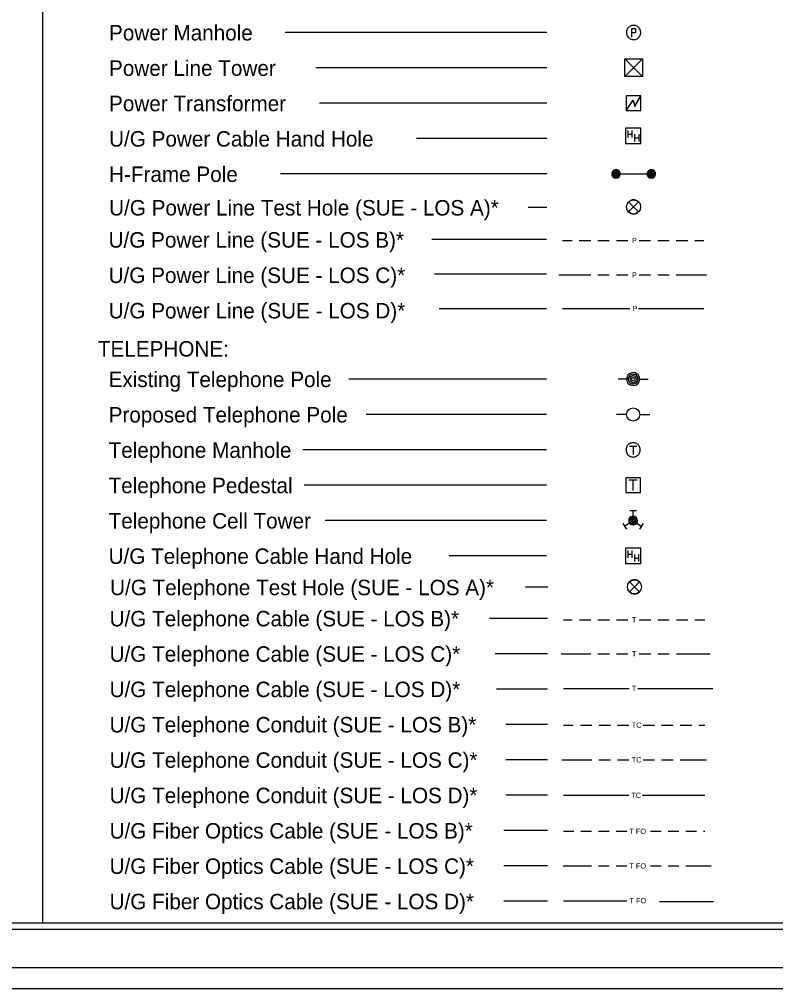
# Model space of a CAD drawing. Extents: x 811508 to 813252, y 647626 to 648754.
# Drawn here: x 812366 to 812809, y 647626 to 648193 of the extents above; entities that cross this region are included whole.
import ezdxf

# ---------------------------------------------------------------- set-up
doc = ezdxf.new("R2010")
doc.units = 0
for name, color, linetype in [('Exist Utilities Power Test Hole SUE LOS A CELL', 7, 'Continuous'), ('Exist Utilities Telephone Test Hole SUE LOS A CELL', 7, 'Continuous'), ('Sheet Cutting Line CELL', 7, 'Continuous'), ('Sheet Plot Border Inside CELL', 7, 'Continuous'), ('Sheet Plot Border Outside CELL', 7, 'Continuous'), ('Sheet_Plan', 7, 'Continuous'), ('Sheet_Symbology', 7, 'Continuous'), ('z - Construction', 7, 'Continuous')]:
    doc.layers.add(name, color=color, linetype=linetype)

msp = doc.modelspace()

# ---------------------------------------------------------------- linework, layer by layer
at = {"layer": 'Exist Utilities Power Test Hole SUE LOS A CELL'}
for points in [[(812728.98, 648086.07), (812723.13, 648080.22), (812726.06, 648083.15), (812723.13, 648086.07), (812728.98, 648080.22)], [(812723.13, 648086.07), (812726.06, 648083.15), (812728.98, 648086.07)], [(812728.98, 648080.22), (812726.06, 648083.15), (812723.13, 648080.22)]]:
    msp.add_lwpolyline(points, dxfattribs=at)
msp.add_circle((812726.06, 648083.15), 4.14, dxfattribs=at)
for start, end in [(45, 135), (225, 315)]:
    msp.add_arc((812726.06, 648083.15), 4.14, start, end, dxfattribs=at)
at = {"layer": 'Exist Utilities Telephone Test Hole SUE LOS A CELL'}
for points in [[(812729.47, 647863.71), (812723.62, 647857.86), (812726.55, 647860.78), (812723.62, 647863.71), (812729.47, 647857.86)], [(812723.62, 647863.71), (812726.55, 647860.78), (812729.47, 647863.71)], [(812729.47, 647857.86), (812726.55, 647860.78), (812723.62, 647857.86)]]:
    msp.add_lwpolyline(points, dxfattribs=at)
msp.add_circle((812726.55, 647860.78), 4.14, dxfattribs=at)
for start, end in [(45, 135), (225, 315)]:
    msp.add_arc((812726.55, 647860.78), 4.14, start, end, dxfattribs=at)
at = {"layer": 'Sheet Cutting Line CELL'}
msp.add_line((811533.6, 647637.99), (813217.6, 647637.99), dxfattribs=at)
at = {"layer": 'Sheet Plot Border Inside CELL'}
msp.add_lwpolyline([(811546.6, 647660.44), (813213.1, 647660.44), (813213.1, 648715.54), (811546.6, 648715.54)], close=True, dxfattribs=at)
at = {"layer": 'Sheet Plot Border Outside CELL'}
msp.add_lwpolyline([(811533.6, 647637.99), (813217.6, 647637.99), (813217.6, 648737.99), (811533.6, 648737.99)], close=True, dxfattribs=at)
at = {"layer": 'Sheet_Plan'}
msp.add_line((811546.61, 647664.09), (813213.5, 647664.09), dxfattribs=at)
at = {"layer": 'Sheet_Symbology'}
for p, q in [((812727.26, 648187.18), (812727.26, 648185.4)), ((812675.36, 648185.26), (812522.02, 648185.26)), ((812726.92, 648185.06), (812725.04, 648185.06)), ((812731.28, 648169.76), (812720.94, 648159.42)), ((812731.28, 648159.42), (812720.94, 648169.76)), ((812675.36, 648164.56), (812540.12, 648164.56)), ((812675.36, 648143.86), (812542.22, 648143.86)), ((812722.69, 648127.92), (812722.69, 648123.75)), ((812722.69, 648125.79), (812725.08, 648125.79)), ((812725.08, 648127.92), (812725.08, 648123.75)), ((812726.68, 648125.65), (812726.68, 648121.48)), ((812726.68, 648123.52), (812729.06, 648123.52)), ((812729.06, 648125.65), (812729.06, 648121.48)), ((812675.36, 648123.17), (812598.88, 648123.17)), ((812675.36, 648102.47), (812519.4, 648102.47)), ((812715.73, 648102.47), (812736.43, 648102.47)), ((812675.36, 648082.83), (812664.35, 648082.83)), ((812675.07, 648064.02), (812607.88, 648064.02)), ((812684.4, 648063.52), (812690.09, 648063.52)), ((812694.23, 648063.52), (812700.96, 648063.52)), ((812705.1, 648063.52), (812711.83, 648063.52)), ((812715.97, 648063.52), (812722.69, 648063.52)), ((812729.32, 648063.52), (812736.05, 648063.52)), ((812740.19, 648063.52), (812746.91, 648063.52)), ((812751.05, 648063.52), (812757.78, 648063.52)), ((812761.92, 648063.52), (812767.2, 648063.52)), ((812675.07, 648043.72), (812609.48, 648043.72)), ((812682.31, 648043.33), (812700.96, 648043.33)), ((812705.1, 648043.33), (812711.83, 648043.33)), ((812715.97, 648043.33), (812722.69, 648043.33)), ((812729.32, 648043.33), (812736.05, 648043.33)), ((812740.19, 648043.33), (812746.91, 648043.33)), ((812751.05, 648043.33), (812768.68, 648043.33)), ((812675.07, 648023.42), (812612.26, 648023.42)), ((812684.4, 648023.7), (812723.82, 648023.7)), ((812728.99, 648023.7), (812767.2, 648023.7)), ((812675.07, 647982.38), (812559.27, 647982.38)), ((812721.98, 647982.38), (812717.01, 647982.38)), ((812729.62, 647982.38), (812734.59, 647982.38)), ((812675.07, 647961.68), (812569.44, 647961.68)), ((812721.96, 647961.67), (812716.14, 647961.67)), ((812729.72, 647961.67), (812735.54, 647961.67)), ((812727.95, 647942.93), (812723.68, 647942.93)), ((812725.8, 647942.93), (812725.8, 647938.22)), ((812675.07, 647940.98), (812532.39, 647940.98)), ((812675.07, 647920.28), (812533.11, 647920.28)), ((812723.38, 647923.4), (812728.22, 647923.4)), ((812725.8, 647917.16), (812725.8, 647923.4)), ((812723.86, 647905.44), (812727.74, 647905.44)), ((812725.8, 647902.13), (812725.8, 647905.44)), ((812675.07, 647899.58), (812545.47, 647899.58)), ((812722.12, 647894.64), (812719.89, 647897.82)), ((812723.72, 647898.13), (812721.01, 647896.23)), ((812727.89, 647898.13), (812730.6, 647896.23)), ((812731.71, 647897.82), (812729.49, 647894.64)), ((812722.63, 647882.01), (812722.63, 647877.84)), ((812722.63, 647879.89), (812725.01, 647879.89)), ((812725.01, 647882.01), (812725.01, 647877.84)), ((812726.61, 647879.74), (812726.61, 647875.57)), ((812728.99, 647879.74), (812728.99, 647875.57)), ((812675.07, 647878.88), (812618.11, 647878.88)), ((812726.61, 647877.62), (812728.99, 647877.62)), ((812675.92, 647860.59), (812662.82, 647860.59)), ((812675.64, 647842.35), (812641.71, 647842.35)), ((812684.97, 647841.52), (812690.17, 647841.52)), ((812694.31, 647841.52), (812701.03, 647841.52)), ((812705.17, 647841.52), (812711.9, 647841.52)), ((812716.04, 647841.52), (812722.77, 647841.52)), ((812729.39, 647841.52), (812736.12, 647841.52)), ((812740.26, 647841.52), (812746.99, 647841.52)), ((812751.13, 647841.52), (812757.85, 647841.52)), ((812761.99, 647841.52), (812767.76, 647841.52)), ((812675.64, 647821.65), (812644.98, 647821.65)), ((812683.67, 647821.65), (812701.03, 647821.65)), ((812705.17, 647821.65), (812711.9, 647821.65)), ((812716.04, 647821.65), (812722.77, 647821.65)), ((812729.39, 647821.65), (812736.12, 647821.65)), ((812740.26, 647821.65), (812746.99, 647821.65)), ((812751.13, 647821.65), (812770.83, 647821.65)), ((812675.64, 647800.95), (812645.77, 647800.95)), ((812684.97, 647801.31), (812723.39, 647801.31)), ((812728.56, 647801.31), (812772.43, 647801.31)), ((812675.64, 647780.25), (812651.36, 647780.25)), ((812684.97, 647779.81), (812690.75, 647779.81)), ((812694.89, 647779.81), (812701.62, 647779.81)), ((812705.76, 647779.81), (812712.48, 647779.81)), ((812716.62, 647779.81), (812723.35, 647779.81)), ((812731.63, 647779.81), (812738.36, 647779.81)), ((812742.5, 647779.81), (812749.22, 647779.81)), ((812753.36, 647779.81), (812760.09, 647779.81)), ((812764.23, 647779.81), (812767.76, 647779.81)), ((812675.64, 647759.55), (812651.36, 647759.55)), ((812683.98, 647759.55), (812701.62, 647759.55)), ((812705.76, 647759.55), (812712.48, 647759.55)), ((812716.62, 647759.55), (812723.35, 647759.55)), ((812731.63, 647759.55), (812738.36, 647759.55)), ((812742.5, 647759.55), (812749.22, 647759.55)), ((812753.36, 647759.55), (812768.76, 647759.55)), ((812675.64, 647738.85), (812651.36, 647738.85)), ((812684.97, 647738.8), (812723.35, 647738.8)), ((812731.11, 647738.8), (812767.76, 647738.8)), ((812675.64, 647718.15), (812650.15, 647718.15)), ((812684.97, 647717.7), (812691.01, 647717.7)), ((812695.15, 647717.7), (812701.36, 647717.7)), ((812705.5, 647717.7), (812711.71, 647717.7)), ((812715.85, 647717.7), (812722.06, 647717.7)), ((812736.03, 647717.7), (812742.24, 647717.7)), ((812746.38, 647717.7), (812752.59, 647717.7)), ((812756.73, 647717.7), (812762.94, 647717.7)), ((812767.08, 647717.7), (812767.76, 647717.7)), ((812675.64, 647697.45), (812650.15, 647697.45)), ((812684.78, 647697.45), (812701.36, 647697.45)), ((812705.5, 647697.45), (812711.71, 647697.45)), ((812715.85, 647697.45), (812722.06, 647697.45)), ((812736.03, 647697.45), (812742.24, 647697.45)), ((812746.38, 647697.45), (812752.59, 647697.45)), ((812756.73, 647697.45), (812771.54, 647697.45)), ((812675.64, 647676.75), (812650.15, 647676.75)), ((812684.97, 647677.09), (812722.1, 647677.09)), ((812741.24, 647676.7), (812772.94, 647676.7))]:
    msp.add_line(p, q, dxfattribs=at)
for points in [[(812726.08, 648189.46), (812725.54, 648189.43), (812725.04, 648189.33), (812724.54, 648189.16), (812724.07, 648188.93), (812723.63, 648188.66), (812723.23, 648188.32), (812722.85, 648187.92), (812722.55, 648187.52), (812722.28, 648187.05), (812722.12, 648186.54), (812721.98, 648186.04), (812721.91, 648185.53), (812721.91, 648184.99), (812721.98, 648184.49), (812722.12, 648183.95), (812722.28, 648183.48), (812722.55, 648183.01), (812722.85, 648182.61), (812723.23, 648182.2), (812723.63, 648181.87), (812724.07, 648181.6), (812724.54, 648181.36), (812725.04, 648181.2), (812725.58, 648181.1), (812726.08, 648181.06), (812726.62, 648181.1), (812727.12, 648181.2), (812727.63, 648181.36), (812728.1, 648181.6), (812728.54, 648181.87), (812728.94, 648182.2), (812729.31, 648182.61), (812729.61, 648183.01), (812729.88, 648183.48), (812730.05, 648183.99), (812730.18, 648184.49), (812730.25, 648184.99), (812730.25, 648185.53), (812730.18, 648186.04), (812730.05, 648186.57), (812729.88, 648187.05), (812729.61, 648187.52), (812729.31, 648187.92), (812728.94, 648188.32), (812728.54, 648188.66), (812728.1, 648188.93), (812727.63, 648189.16), (812727.12, 648189.33), (812726.59, 648189.43), (812726.08, 648189.46)], [(812725.04, 648182.57), (812725.04, 648185.06), (812725.04, 648187.52), (812726.92, 648187.52)], [(812726.92, 648187.52), (812727.06, 648187.48), (812727.16, 648187.41), (812727.23, 648187.31), (812727.26, 648187.18)], [(812727.26, 648185.4), (812727.23, 648185.26), (812727.16, 648185.16), (812727.06, 648185.1), (812726.92, 648185.06)], [(812731.28, 648159.42), (812720.94, 648159.42), (812720.94, 648169.76), (812731.28, 648169.76), (812731.28, 648159.42), (812720.94, 648159.42), (812720.94, 648169.76), (812731.28, 648169.76), (812731.28, 648159.42)], [(812721.77, 648139.55), (812725.84, 648145.41), (812726.83, 648142.22), (812730.4, 648148.18)], [(812721.77, 648139.55), (812725.88, 648145.64), (812726.8, 648141.98), (812730.4, 648148.18)], [(812721.77, 648139.55), (812730.4, 648139.55), (812730.4, 648148.18), (812721.77, 648148.18), (812721.77, 648139.55)], [(812721.41, 648120.33), (812730.32, 648120.33), (812730.32, 648129.24), (812721.41, 648129.24), (812721.41, 648120.33)], [(812717.62, 648102.47), (812717.57, 648102.92), (812717.41, 648103.33), (812717.16, 648103.69), (812716.85, 648103.99), (812716.5, 648104.2), (812716.04, 648104.3), (812715.63, 648104.35), (812715.17, 648104.25), (812714.76, 648104.1), (812714.46, 648103.84), (812714.15, 648103.48), (812713.95, 648103.13), (812713.85, 648102.67), (812713.85, 648102.26), (812713.95, 648101.8), (812714.15, 648101.45), (812714.46, 648101.09), (812714.76, 648100.84), (812715.17, 648100.68), (812715.63, 648100.58), (812716.04, 648100.63), (812716.5, 648100.73), (812716.85, 648100.94), (812717.16, 648101.24), (812717.41, 648101.6), (812717.57, 648102.01), (812717.62, 648102.47)], [(812717.01, 648102.47), (812716.95, 648102.82), (812716.8, 648103.18), (812716.55, 648103.43), (812716.24, 648103.64), (812715.94, 648103.74), (812715.53, 648103.74), (812715.22, 648103.64), (812714.92, 648103.43), (812714.66, 648103.18), (812714.51, 648102.82), (812714.46, 648102.47), (812714.51, 648102.11), (812714.66, 648101.75), (812714.92, 648101.5), (812715.22, 648101.29), (812715.53, 648101.19), (812715.94, 648101.19), (812716.24, 648101.29), (812716.55, 648101.5), (812716.8, 648101.75), (812716.95, 648102.11), (812717.01, 648102.47)], [(812716.34, 648102.47), (812716.29, 648102.72), (812716.14, 648102.92), (812715.94, 648103.03), (812715.68, 648103.08), (812715.43, 648102.98), (812715.22, 648102.82), (812715.12, 648102.57), (812715.12, 648102.36), (812715.22, 648102.11), (812715.43, 648101.96), (812715.68, 648101.85), (812715.94, 648101.91), (812716.14, 648102.01), (812716.29, 648102.21), (812716.34, 648102.47)], [(812738.32, 648102.47), (812738.27, 648102.92), (812738.11, 648103.33), (812737.86, 648103.69), (812737.55, 648103.99), (812737.2, 648104.2), (812736.74, 648104.3), (812736.33, 648104.35), (812735.87, 648104.25), (812735.46, 648104.1), (812735.16, 648103.84), (812734.85, 648103.48), (812734.65, 648103.13), (812734.55, 648102.67), (812734.55, 648102.26), (812734.65, 648101.8), (812734.85, 648101.45), (812735.16, 648101.09), (812735.46, 648100.84), (812735.87, 648100.68), (812736.33, 648100.58), (812736.74, 648100.63), (812737.2, 648100.73), (812737.55, 648100.94), (812737.86, 648101.24), (812738.11, 648101.6), (812738.27, 648102.01), (812738.32, 648102.47)], [(812737.7, 648102.47), (812737.65, 648102.82), (812737.5, 648103.18), (812737.25, 648103.43), (812736.94, 648103.64), (812736.64, 648103.74), (812736.23, 648103.74), (812735.92, 648103.64), (812735.62, 648103.43), (812735.36, 648103.18), (812735.21, 648102.82), (812735.16, 648102.47), (812735.21, 648102.11), (812735.36, 648101.75), (812735.62, 648101.5), (812735.92, 648101.29), (812736.23, 648101.19), (812736.64, 648101.19), (812736.94, 648101.29), (812737.25, 648101.5), (812737.5, 648101.75), (812737.65, 648102.11), (812737.7, 648102.47)], [(812737.04, 648102.47), (812736.99, 648102.72), (812736.84, 648102.92), (812736.64, 648103.03), (812736.38, 648103.08), (812736.13, 648102.98), (812735.92, 648102.82), (812735.82, 648102.57), (812735.82, 648102.36), (812735.92, 648102.11), (812736.13, 648101.96), (812736.38, 648101.85), (812736.64, 648101.91), (812736.84, 648102.01), (812736.99, 648102.21), (812737.04, 648102.47)], [(812728.63, 647982.38), (812728.55, 647983.07), (812728.32, 647983.68), (812727.94, 647984.21), (812727.48, 647984.67), (812726.95, 647984.98), (812726.26, 647985.13), (812725.65, 647985.21), (812724.96, 647985.05), (812724.35, 647984.82), (812723.89, 647984.44), (812723.43, 647983.91), (812723.13, 647983.37), (812722.97, 647982.68), (812722.97, 647982.07), (812723.13, 647981.39), (812723.43, 647980.85), (812723.89, 647980.32), (812724.35, 647979.93), (812724.96, 647979.7), (812725.65, 647979.55), (812726.26, 647979.63), (812726.95, 647979.78), (812727.48, 647980.09), (812727.94, 647980.55), (812728.32, 647981.08), (812728.55, 647981.69), (812728.63, 647982.38)], [(812727.71, 647982.38), (812727.63, 647982.91), (812727.4, 647983.45), (812727.02, 647983.83), (812726.56, 647984.14), (812726.11, 647984.29), (812725.49, 647984.29), (812725.03, 647984.14), (812724.58, 647983.83), (812724.2, 647983.45), (812723.97, 647982.91), (812723.89, 647982.38), (812723.97, 647981.84), (812724.2, 647981.31), (812724.58, 647980.93), (812725.03, 647980.62), (812725.49, 647980.47), (812726.11, 647980.47), (812726.56, 647980.62), (812727.02, 647980.93), (812727.4, 647981.31), (812727.63, 647981.84), (812727.71, 647982.38)], [(812726.72, 647982.38), (812726.64, 647982.76), (812726.41, 647983.07), (812726.11, 647983.22), (812725.72, 647983.3), (812725.34, 647983.14), (812725.03, 647982.91), (812724.88, 647982.53), (812724.88, 647982.22), (812725.03, 647981.84), (812725.34, 647981.61), (812725.72, 647981.46), (812726.11, 647981.54), (812726.41, 647981.69), (812726.64, 647982), (812726.72, 647982.38)], [(812725.8, 647945.18), (812725.26, 647945.15), (812724.76, 647945.05), (812724.25, 647944.88), (812723.78, 647944.64), (812723.35, 647944.37), (812722.94, 647944.04), (812722.57, 647943.64), (812722.27, 647943.23), (812722, 647942.76), (812721.83, 647942.26), (812721.7, 647941.75), (812721.63, 647941.25), (812721.63, 647940.71), (812721.7, 647940.21), (812721.83, 647939.67), (812722, 647939.2), (812722.27, 647938.73), (812722.57, 647938.32), (812722.94, 647937.92), (812723.35, 647937.59), (812723.78, 647937.32), (812724.25, 647937.08), (812724.76, 647936.91), (812725.3, 647936.81), (812725.8, 647936.78), (812726.34, 647936.81), (812726.84, 647936.91), (812727.35, 647937.08), (812727.82, 647937.32), (812728.25, 647937.59), (812728.66, 647937.92), (812729.03, 647938.32), (812729.33, 647938.73), (812729.6, 647939.2), (812729.77, 647939.7), (812729.9, 647940.21), (812729.97, 647940.71), (812729.97, 647941.25), (812729.9, 647941.75), (812729.77, 647942.29), (812729.6, 647942.76), (812729.33, 647943.23), (812729.03, 647943.64), (812728.66, 647944.04), (812728.25, 647944.37), (812727.82, 647944.64), (812727.35, 647944.88), (812726.84, 647945.05), (812726.3, 647945.15), (812725.8, 647945.18)], [(812721.44, 647915.92), (812730.16, 647915.92), (812730.16, 647924.64), (812721.44, 647924.64), (812721.44, 647915.92)], [(812727.69, 647899.58), (812727.63, 647900.04), (812727.48, 647900.45), (812727.23, 647900.8), (812726.92, 647901.11), (812726.56, 647901.31), (812726.1, 647901.42), (812725.7, 647901.47), (812725.24, 647901.36), (812724.83, 647901.21), (812724.53, 647900.96), (812724.22, 647900.6), (812724.02, 647900.24), (812723.91, 647899.79), (812723.91, 647899.38), (812724.02, 647898.92), (812724.22, 647898.56), (812724.53, 647898.21), (812724.83, 647897.95), (812725.24, 647897.8), (812725.7, 647897.7), (812726.1, 647897.75), (812726.56, 647897.85), (812726.92, 647898.05), (812727.23, 647898.36), (812727.48, 647898.72), (812727.63, 647899.12), (812727.69, 647899.58)], [(812727.07, 647899.58), (812727.02, 647899.94), (812726.87, 647900.29), (812726.61, 647900.55), (812726.31, 647900.75), (812726, 647900.85), (812725.6, 647900.85), (812725.29, 647900.75), (812724.98, 647900.55), (812724.73, 647900.29), (812724.58, 647899.94), (812724.53, 647899.58), (812724.58, 647899.22), (812724.73, 647898.87), (812724.98, 647898.61), (812725.29, 647898.41), (812725.6, 647898.31), (812726, 647898.31), (812726.31, 647898.41), (812726.61, 647898.61), (812726.87, 647898.87), (812727.02, 647899.22), (812727.07, 647899.58)], [(812726.41, 647899.58), (812726.36, 647899.84), (812726.21, 647900.04), (812726, 647900.14), (812725.75, 647900.19), (812725.49, 647900.09), (812725.29, 647899.94), (812725.19, 647899.68), (812725.19, 647899.48), (812725.29, 647899.22), (812725.49, 647899.07), (812725.75, 647898.97), (812726, 647899.02), (812726.21, 647899.12), (812726.36, 647899.33), (812726.41, 647899.58)], [(812721.34, 647874.43), (812730.25, 647874.43), (812730.25, 647883.34), (812721.34, 647883.34), (812721.34, 647874.43)]]:
    msp.add_lwpolyline(points, dxfattribs=at)
for points in [[(812715.73, 648099.92), (812716.8, 648100.12), (812717.52, 648100.63), (812718.08, 648101.35), (812718.28, 648102.31), (812718.18, 648103.23), (812717.67, 648104.15), (812716.65, 648104.91), (812715.48, 648105.01), (812714.46, 648104.71), (812713.64, 648103.99), (812713.24, 648103.03), (812713.24, 648101.91), (812713.64, 648100.94), (812714.56, 648100.17)], [(812736.43, 648099.92), (812737.5, 648100.12), (812738.21, 648100.63), (812738.78, 648101.35), (812738.98, 648102.31), (812738.88, 648103.23), (812738.37, 648104.15), (812737.35, 648104.91), (812736.18, 648105.01), (812735.16, 648104.71), (812734.34, 648103.99), (812733.94, 648103.03), (812733.94, 648101.91), (812734.34, 648100.94), (812735.26, 648100.17)], [(812725.8, 647978.56), (812727.4, 647978.86), (812728.47, 647979.63), (812729.31, 647980.7), (812729.62, 647982.15), (812729.47, 647983.53), (812728.7, 647984.9), (812727.18, 647986.05), (812725.42, 647986.2), (812723.89, 647985.74), (812722.67, 647984.67), (812722.06, 647983.22), (812722.06, 647981.54), (812722.67, 647980.09), (812724.04, 647978.94)], [(812725.8, 647897.03), (812726.87, 647897.24), (812727.58, 647897.75), (812728.14, 647898.46), (812728.35, 647899.43), (812728.24, 647900.35), (812727.74, 647901.26), (812726.72, 647902.03), (812725.55, 647902.13), (812724.53, 647901.82), (812723.71, 647901.11), (812723.3, 647900.14), (812723.3, 647899.02), (812723.71, 647898.05), (812724.63, 647897.29)]]:
    msp.add_lwpolyline(points, close=True, dxfattribs=at)
msp.add_circle((812725.8, 647961.68), 3.88, dxfattribs=at)
at = {"layer": 'z - Construction'}
for p, q in [((812380.06, 648715.54), (812380.04, 647664.09)), ((811508.14, 647625.63), (813251.99, 647625.63))]:
    msp.add_line(p, q, dxfattribs=at)

# ---------------------------------------------------------------- texts
at = {"layer": 'Sheet_Symbology'}
for s, height, p in [('Power Manhole', 9.056, (812418.97, 648180.57)), ('Power Line Tower', 9.056, (812418.97, 648159.88)), ('Power Transformer', 9.056, (812418.96, 648139.18)), ('U/G Power Cable Hand Hole', 9.056, (812418.98, 648118.47)), ('H-Frame Pole', 9.056, (812418.98, 648097.77)), ('U/G Power Line Test Hole (SUE - LOS A)*', 9.056, (812418.98, 648078.13)), ('U/G Power Line (SUE - LOS B)*', 9.056, (812418.7, 648059.33)), ('P', 3.1, (812725.08, 648061.96)), ('U/G Power Line (SUE - LOS C)*', 9.056, (812418.72, 648038.62)), ('P', 3.1, (812725.08, 648041.77)), ('U/G Power Line (SUE - LOS D)*', 9.056, (812418.75, 648017.9)), ('P', 3.1, (812725.48, 648022.15)), ('TELEPHONE:', 9.056, (812412.42, 647995.58)), ('Existing Telephone Pole', 9.056, (812418.7, 647977.68)), ('Proposed Telephone Pole', 9.056, (812418.7, 647956.98)), ('Telephone Manhole', 9.056, (812418.7, 647936.28)), ('Telephone Pedestal', 9.056, (812418.7, 647915.58)), ('Telephone Cell Tower', 9.056, (812418.71, 647894.89)), ('U/G Telephone Cable Hand Hole', 9.056, (812418.71, 647874.19)), ('U/G Telephone Test Hole (SUE - LOS A)*', 9.056, (812419.56, 647855.89)), ('U/G Telephone Cable (SUE - LOS B)*', 9.056, (812419.28, 647837.65)), ('T', 3.1, (812725.1, 647839.97)), ('U/G Telephone Cable (SUE - LOS C)*', 9.056, (812419.28, 647816.95)), ('T', 3.1, (812725.1, 647820.1)), ('U/G Telephone Cable (SUE - LOS D)*', 9.056, (812419.28, 647796.25)), ('T', 3.1, (812724.99, 647799.76)), ('U/G Telephone Conduit (SUE - LOS B)*', 9.056, (812419.28, 647775.56)), ('TC', 3.105, (812725.01, 647778.26)), ('U/G Telephone Conduit (SUE - LOS C)*', 9.056, (812419.28, 647754.86)), ('TC', 3.105, (812725.01, 647758)), ('U/G Telephone Conduit (SUE - LOS D)*', 9.056, (812419.28, 647734.16)), ('TC', 3.105, (812724.75, 647737.25)), ('U/G Fiber Optics Cable (SUE - LOS B)*', 9.056, (812419.28, 647713.46)), ('T FO', 3.105, (812723.61, 647716.15)), ('U/G Fiber Optics Cable (SUE - LOS C)*', 9.056, (812419.28, 647692.76)), ('T FO', 3.105, (812723.61, 647695.9)), ('U/G Fiber Optics Cable (SUE - LOS D)*', 9.056, (812419.28, 647672.06)), ('T FO', 3.105, (812723.65, 647675.54))]:
    msp.add_text(s, height=height, dxfattribs=at).set_placement(p)

doc.saveas('drawing.dxf')
